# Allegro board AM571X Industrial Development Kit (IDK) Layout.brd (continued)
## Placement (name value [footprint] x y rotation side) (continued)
R97  0  [SM-7351-RES-0603]  23.49 123.78 270 top
R98  0  [SM-7351-RES-0402]  25.91 119.84 0 bottom
R99  49.9  [SM-7351-RES-0402]  17.84 123.53 0 bottom
R100  49.9  [SM-7351-RES-0402]  19.87 123.53 180 bottom
R101  49.9  [SM-7351-RES-0402]  22.61 127.21 90 bottom
R102  49.9  [SM-7351-RES-0402]  22.61 129.24 270 bottom
R103  4.87K  [SM-7351-RES-0402]  23.49 121.11 180 top
R104  2.2K  [SM-7351-RES-0402]  23.37 113.79 180 top
R106  0  [SM-7351-RES-0402]  6.48 129.88 90 bottom
R107  10K  [SM-7351-RES-0402]  43.05 86.82 270 bottom
R108  2.2K  [SM-7351-RES-0402]  23.37 116.08 180 top
R109  2.2K  [SM-7351-RES-0402]  23.37 114.94 180 top
R110  2.2K  [SM-7351-RES-0402]  23.37 111.51 180 top
R111  2.2K  [SM-7351-RES-0402]  23.37 112.65 180 top
R112  0  [SM-7351-RES-0402]  44.7 87.33 0 bottom
R113  62,1%  [SM-7351-RES-0402]  140.34 14.86 180 top
R114  0  [SM-7351-RES-0402]  141.61 10.41 0 top
R115  0  [SM-7351-RES-0402]  43.43 83.14 90 top
R116  2.2K  [SM-7351-RES-0402]  141.61 11.43 0 top
R117  0  [SM-7351-RES-0402]  45.97 83.14 90 top
R118  0  [SM-7351-RES-0402]  48.51 83.14 90 top
R119  0  [SM-7351-RES-0402]  51.05 83.14 90 top
R120  2.2K  [SM-7351-RES-0402]  29.59 93.17 270 top
R121  0  [SM-7351-RES-0402]  23.37 99.27 270 bottom
R122  0  [SM-7351-RES-0402]  7.7 117.55 180 bottom
R123  0  [SM-7351-RES-0402]  114.68 99.78 270 top
R124  0  [SM-7351-RES-0402]  118.49 99.9 270 top
R125  0  [SM-7351-RES-0402]  112.27 99.82 270 top
R126  0  [SM-7351-RES-0402]  119.63 99.95 270 top
R127  0  [SM-7351-RES-0402]  116.08 99.78 270 top
R128  0  [SM-7351-RES-0402]  117.47 99.9 270 top
R129  0  [SM-7351-RES-0402]  37.34 95.76 0 top
R130  0  [SM-7351-RES-0402]  40.51 96.52 0 top
R131  2.2K  [SM-7351-RES-0402]  27.69 95.33 270 top
R132  0  [SM-7351-RES-0402]  37.34 98.55 0 top
R133  0  [SM-7351-RES-0402]  34.42 101.35 180 bottom
R134  0  [SM-7351-RES-0402]  7.19 95.58 180 bottom
R135  0  [SM-7351-RES-0402]  34.42 102.49 180 bottom
R136  0  [SM-7351-RES-0402]  40 103 0 top
R137  0  [SM-7351-RES-0402]  37.34 104.77 0 top
R138  0  [SM-7351-RES-0603]  6.48 108.67 270 bottom
R139  0  [SM-7351-RES-0402]  37.34 97.28 0 top
R140  0  [SM-7351-RES-0402]  30.61 95.33 270 top
R141  0  [SM-7351-RES-0603]  29.34 101.55 270 bottom
R142  0  [SM-7351-RES-0402]  29.59 95.33 270 top
R143  49.9  [SM-7351-RES-0402]  24.38 106.89 270 top
R144  49.9  [SM-7351-RES-0402]  24.38 104.86 90 top
R145  49.9  [SM-7351-RES-0402]  24.38 102.82 270 top
R146  49.9  [SM-7351-RES-0402]  24.38 100.67 90 top
R147  4.87K  [SM-7351-RES-0402]  26.03 97.74 0 top
R148  0  [SM-7351-RES-0402]  40.51 100.71 0 top
R149  10K  [SM-7351-RES-0402]  186.72 83.14 180 bottom
R151  0  [SM-7351-RES-0402]  6.43 105.74 90 bottom
R152  2.2K  [SM-7351-RES-0402]  37.34 100.08 0 top
R153  10K  [SM-7351-RES-0402]  33.15 89.74 90 bottom
R154  0  [SM-7351-RES-0402]  34.8 89.24 0 bottom
R155  2.2K  [SM-7351-RES-0402]  37.34 103.76 180 top
R156  2.2K  [SM-7351-RES-0402]  40 104.01 180 top
R157  2.2K  [SM-7351-RES-0402]  37.34 102.36 180 top
R158  2.2K  [SM-7351-RES-0402]  37.34 101.3 180 top
R159  2.2K  [SM-7351-RES-0402]  28.19 77.55 270 top
R160  0  [SM-7351-RES-0402]  23.37 75.14 270 bottom
R161  0  [SM-7351-RES-0402]  7.75 93.43 180 bottom
R162  0  [SM-7351-RES-0402]  124.08 82.76 180 top
R163  0  [SM-7351-RES-0402]  124.08 81.62 180 top
R164  0  [SM-7351-RES-0402]  124.08 83.9 180 top
R165  0  [SM-7351-RES-0402]  37.34 77.68 0 top
R166  0  [SM-7351-RES-0402]  37.34 78.82 0 top
R167  0  [SM-7351-RES-0402]  120.27 83.57 180 top
R168  0  [SM-7351-RES-0402]  120.27 81.66 180 top
R169  0  [SM-7351-RES-0402]  124.08 85.17 180 top
R170  0  [SM-7351-RES-0402]  37.34 81.11 0 top
R171  0  [SM-7351-RES-0402]  37.34 83.52 0 bottom
R172  0  [SM-7351-RES-0402]  7.24 71.46 180 bottom
R173  0  [SM-7351-RES-0402]  37.34 84.66 0 bottom
R174  0  [SM-7351-RES-0402]  37.34 85.81 0 bottom
R175  0  [SM-7351-RES-0402]  37.34 86.95 0 bottom
R176  0  [SM-7351-RES-0402]  6.48 83.77 270 bottom
R177  0  [SM-7351-RES-0402]  37.34 79.96 0 top
R178  DNI  [SM-7351-RES-0402]  124.08 80.35 180 top
R179  0  [SM-7351-RES-0402]  30.61 77.55 270 top
R180  0  [SM-7351-RES-0603]  29.34 83.77 270 bottom
R181  0  [SM-7351-RES-0402]  29.59 77.55 270 top
R182  49.9  [SM-7351-RES-0402]  24.38 89.11 270 top
R183  49.9  [SM-7351-RES-0402]  24.38 87.08 90 top
R184  49.9  [SM-7351-RES-0402]  24.38 85.04 270 top
R185  49.9  [SM-7351-RES-0402]  24.38 82.89 90 top
R186  4.87K  [SM-7351-RES-0402]  28.19 77.55 90 bottom
R187  2.2K  [SM-7351-RES-0402]  37.34 82.5 180 top
R188  0  [SM-7351-RES-0402]  120.27 78.06 180 top
R189  0  [SM-7351-RES-0402]  6.48 81.62 90 bottom
R190  10K  [SM-7351-RES-0402]  28.19 71.2 90 bottom
R191  2.2K  [SM-7351-RES-0402]  37.34 86.95 180 top
R192  2.2K  [SM-7351-RES-0402]  37.34 85.81 180 top
R193  2.2K  [SM-7351-RES-0402]  37.34 84.66 180 top
R194  2.2K  [SM-7351-RES-0402]  37.34 83.52 180 top
R195  0  [SM-7351-RES-0402]  29.84 70.69 0 bottom
R196  0  [SM-7351-RES-0402]  43.31 74.5 90 top
R197  0  [SM-7351-RES-0402]  45.85 74.5 90 top
R198  0  [SM-7351-RES-0402]  48.39 74.5 90 top
R199  0  [SM-7351-RES-0402]  50.93 74.5 90 top
R200  2.2K  [SM-7351-RES-0402]  28.19 52.79 270 top
R201  2.2K  [SM-7351-RES-0402]  29.59 50.63 270 top
R202  0  [SM-7351-RES-0402]  23.37 50.37 270 bottom
R203  0  [SM-7351-RES-0402]  7.75 68.66 180 bottom
R204  0  [SM-7351-RES-0402]  78.36 95.97 0 top
R205  0  [SM-7351-RES-0402]  78.36 98 0 top
R206  0  [SM-7351-RES-0402]  78.36 94.95 0 top
R207  0  [SM-7351-RES-0402]  78.36 93.93 0 top
R208  0  [SM-7351-RES-0402]  78.36 92.92 0 top
R209  0  [SM-7351-RES-0402]  37.34 52.91 0 top
R210  0  [SM-7351-RES-0402]  78.36 96.98 0 top
R211  0  [SM-7351-RES-0402]  37.34 54.06 0 top
R212  0  [SM-7351-RES-0402]  37.34 56.34 0 top
R213  0  [SM-7351-RES-0402]  37.34 58.76 0 bottom
R214  0  [SM-7351-RES-0402]  7.24 46.69 180 bottom
R215  0  [SM-7351-RES-0402]  37.34 59.9 0 bottom
R216  0  [SM-7351-RES-0402]  37.34 61.04 0 bottom
R217  0  [SM-7351-RES-0402]  37.34 62.18 0 bottom
R218  0  [SM-7351-RES-0603]  6.48 59.39 270 bottom
R219  0  [SM-7351-RES-0402]  37.34 55.2 0 top
R220  DNI  [SM-7351-RES-0402]  124.08 74.8 180 top
R221  0  [SM-7351-RES-0402]  30.61 52.79 270 top
R222  0  [SM-7351-RES-0603]  29.34 59.01 270 bottom
R223  0  [SM-7351-RES-0402]  29.59 52.79 270 top
R224  49.9  [SM-7351-RES-0402]  24.38 64.34 270 top
R225  49.9  [SM-7351-RES-0402]  24.38 62.31 90 top
R226  49.9  [SM-7351-RES-0402]  24.38 60.28 270 top
R227  49.9  [SM-7351-RES-0402]  24.38 58.12 90 top
R228  4.87K  [SM-7351-RES-0402]  28.19 52.79 90 bottom
R230  0  [SM-7351-RES-0402]  124.08 77.17 180 top
R231  0  [SM-7351-RES-0402]  6.48 56.6 270 bottom
R232  2.2K  [SM-7351-RES-0402]  37.34 57.74 0 bottom
R233  10K  [SM-7351-RES-0402]  28.19 46.44 90 bottom
R234  0  [SM-7351-RES-0402]  29.84 45.93 0 bottom
R235  2.2K  [SM-7351-RES-0402]  37.34 62.18 180 top
R236  2.2K  [SM-7351-RES-0402]  37.34 61.04 180 top
R237  2.2K  [SM-7351-RES-0402]  37.34 59.9 180 top
R238  2.2K  [SM-7351-RES-0402]  37.34 58.76 180 top
R239  220  [SM-7351-RES-0402]  10.79 4.7 180 bottom
R240  220  [SM-7351-RES-0402]  17.4 4.7 180 bottom
R241  0  [SM-7351-RES-0402]  10.79 3.64 180 bottom
R242  220  [SM-7351-RES-0402]  10.79 11.43 180 bottom
R243  0  [SM-7351-RES-0402]  17.4 3.64 180 bottom
R244  220  [SM-7351-RES-0402]  17.4 11.43 180 bottom
R245  100K  [SM-7351-RES-0402]  10.79 2.62 0 bottom
R246  100K  [SM-7351-RES-0402]  17.4 2.62 0 bottom
R247  0  [SM-7351-RES-0402]  10.79 10.37 0 bottom
R248  0  [SM-7351-RES-0402]  17.4 10.37 0 bottom
R249  220  [SM-7351-RES-0402]  10.79 8 180 bottom
R250  220  [SM-7351-RES-0402]  17.4 8 180 bottom
R251  100K  [SM-7351-RES-0402]  10.79 9.35 0 bottom
R252  100K  [SM-7351-RES-0402]  17.4 9.35 0 bottom
R253  0  [SM-7351-RES-0402]  10.79 6.94 0 bottom
R254  0  [SM-7351-RES-0402]  17.4 6.94 0 bottom
R255  100K  [SM-7351-RES-0402]  10.79 5.92 0 bottom
R256  100K  [SM-7351-RES-0402]  17.4 5.92 0 bottom
R257  0  [SM-7351-RES-0402]  159 142.83 270 top
R258  0  [SM-7351-RES-0402]  162.71 133.56 90 top
R259  10K  [SM-7351-RES-0402]  177.95 133.56 270 bottom
R260  0  [SM-7351-RES-0402]  161.54 142.83 90 top
R261  0  [SM-7351-RES-0402]  164.11 133.56 270 top
R262  0  [SM-7351-RES-0402]  165.38 133.56 90 top
R263  0  [SM-7351-RES-0402]  166.65 133.56 270 top
R264  0  [SM-7351-RES-0402]  167.79 133.56 90 top
R265  0  [SM-7351-RES-0402]  169.19 133.56 270 top
R267  0  [SM-7351-RES-0402]  174.27 133.56 270 top
R269  0  [SM-7351-RES-0402]  176.81 133.56 270 top
R271  0  [SM-7351-RES-0402]  179.35 133.56 270 top
R273  0  [SM-7351-RES-0402]  181.89 133.56 270 top
R274  0  [SM-7351-RES-0402]  180.62 133.56 90 top
R275  0  [SM-7351-RES-0402]  185.57 133.56 90 top
R276  22  [SM-7351-RES-0402]  163.83 144.02 0 bottom
R277  0  [SM-7351-RES-0402]  188.11 133.56 90 top
R278  0  [SM-7351-RES-0603]  29.29 115.5 270 bottom
R279  1.5K  [SM-7351-RES-0402]  41.15 116.41 180 top
R280  100K  [SM-7351-RES-0402]  38.99 110.7 0 bottom
R281  22  [SM-7351-RES-0402]  84.84 103.12 270 top
R282  22  [SM-7351-RES-0402]  86.11 103.12 270 top
R283  22  [SM-7351-RES-0402]  87.38 103.12 270 top
R284  22  [SM-7351-RES-0402]  88.65 103.12 270 top
R285  22  [SM-7351-RES-0402]  36.86 111.76 270 top
R286  22  [SM-7351-RES-0402]  89.92 103.12 270 top
R287  22  [SM-7351-RES-0402]  91.19 103.12 270 top
R288  22  [SM-7351-RES-0402]  38.35 111.76 270 top
R289  22  [SM-7351-RES-0402]  35.46 111.76 270 top
R290  22  [SM-7351-RES-0402]  34.06 111.76 270 top
R291  22  [SM-7351-RES-0402]  32.66 111.76 270 top
R292  22  [SM-7351-RES-0402]  31.27 111.76 270 top
R293  220  [SM-7351-RES-0402]  33.02 145.37 90 bottom
R294  0  [SM-7351-RES-0402]  39.55 113.95 270 top
R295  0  [SM-7351-RES-0402]  41.15 117.43 0 top
R296  220  [SM-7351-RES-0402]  34.16 145.37 90 bottom
R297  4.7K  [SM-7351-RES-0402]  41.15 118.45 0 top
R298  12.1K, 1%  [SM-7351-RES-0402]  41.15 124.54 0 top
R299  10K  [SM-7351-RES-0402]  35.48 113.95 270 top
R300  DNI  [SM-7351-RES-0402]  163.83 145.29 0 bottom
R301  10K  [SM-7351-RES-0402]  34.09 113.95 270 top
R304  1K  [SM-7351-RES-0402]  36.88 113.95 270 top
R305  1M  [SM-7351-RES-0402]  45.5 103.06 270 bottom
R306  10K  [SM-7351-RES-0402]  32.77 114 270 top
R308  0  [SM-7351-RES-0402]  45.5 105.1 270 bottom
R309  10K  [SM-7351-RES-0402]  31.5 114 270 top
R310  33  [SM-7351-RES-0402]  37.21 103.89 180 bottom
R312  0  [SM-7351-RES-0402]  43.81 103.59 270 top
R313  33  [SM-7351-RES-0402]  38 105.1 180 bottom
R314  0  [SM-7351-RES-0402]  42.8 103.59 270 top
R315  33  [SM-7351-RES-0402]  38 107 180 bottom
R317  1K  [SM-7351-RES-0402]  38.28 113.95 270 top
R319  1K  [SM-7351-RES-0402]  28.45 124.03 0 top
R321  1K  [SM-7351-RES-0402]  28.45 121.11 0 top
R322  0  [SM-7351-RES-0603]  50.67 112.22 270 bottom
R324  100K  [SM-7351-RES-0402]  60.71 110.7 0 bottom
R325  22  [SM-7351-RES-0402]  120.27 104.9 270 top
R326  22  [SM-7351-RES-0402]  115.7 104.9 270 top
R327  22  [SM-7351-RES-0402]  117.98 104.9 270 top
R328  22  [SM-7351-RES-0402]  59.56 110.57 270 top
R329  22  [SM-7351-RES-0402]  58.17 110.57 270 top
R330  22  [SM-7351-RES-0402]  121.41 104.9 270 top
R331  22  [SM-7351-RES-0402]  116.84 104.9 270 top
R332  22  [SM-7351-RES-0402]  119.13 104.9 270 top
R333  22  [SM-7351-RES-0402]  56.77 110.57 270 top
R334  22  [SM-7351-RES-0402]  55.37 110.57 270 top
R335  22  [SM-7351-RES-0402]  53.98 110.57 270 top
R336  22  [SM-7351-RES-0402]  52.58 110.57 270 top
R337  220  [SM-7351-RES-0402]  54.74 145.37 90 bottom
R338  0  [SM-7351-RES-0402]  60.83 112.98 270 top
R339  0  [SM-7351-RES-0402]  62.99 117.05 0 top
R340  220  [SM-7351-RES-0402]  55.88 145.37 90 bottom
R341  12.1K, 1%  [SM-7351-RES-0402]  61.72 125.18 90 top
R342  4.7K  [SM-7351-RES-0402]  62.99 118.45 0 top
R343  10K  [SM-7351-RES-0402]  56.77 112.98 270 top
R345  10K  [SM-7351-RES-0402]  55.37 112.98 270 top
R348  1K  [SM-7351-RES-0402]  58.17 112.98 270 top
R349  1M  [SM-7351-RES-0402]  59.18 99.52 270 bottom
R351  0  [SM-7351-RES-0402]  59.18 101.68 270 bottom
R352  10K  [SM-7351-RES-0402]  53.98 112.98 270 top
R353  10K  [SM-7351-RES-0402]  52.58 112.98 270 top
R354  33  [SM-7351-RES-0402]  52.07 96.09 270 bottom
R356  0  [SM-7351-RES-0402]  57.78 106.13 90 bottom
R357  33  [SM-7351-RES-0402]  50.8 96.14 270 bottom
R358  0  [SM-7351-RES-0402]  56.64 106.13 90 bottom
R359  33  [SM-7351-RES-0402]  53.21 106.13 90 bottom
R361  1K  [SM-7351-RES-0402]  59.56 112.98 270 top
R363  1K  [SM-7351-RES-0402]  50.16 124.03 0 top
R364  10K  [SM-7351-RES-0402]  50.16 120.48 0 top
R366  10K  [SM-7351-RES-0402]  178.31 54.95 270 top
R367  0  [SM-7351-RES-0402]  127.89 75.27 180 top
R368  1.2K, MELF  [SMD_MELF0102]  178.97 58.17 180 bottom
R369  0  [SM-7351-RES-0402]  127.89 76.28 180 top
R370  1.2K, MELF  [SMD_MELF0102]  178.97 55.63 180 bottom
R371  0  [SM-7351-RES-0402]  85.47 92.92 0 top
R372  1.2K, MELF  [SMD_MELF0102]  178.97 53.09 180 bottom
R373  1.2K, MELF  [SMD_MELF0102]  178.97 48.01 180 bottom
R374  1.2K, MELF  [SMD_MELF0102]  178.97 50.55 180 bottom
R375  1.2K, MELF  [SMD_MELF0102]  178.97 45.47 180 bottom
R376  1.2K, MELF  [SMD_MELF0102]  178.97 42.93 180 bottom
R377  0  [SM-7351-RES-0402]  121.54 71.33 180 top
R378  1.2K, MELF  [SMD_MELF0102]  178.97 40.39 180 bottom
R379  49.9  [SMD_MELF0102]  187.58 77.6 270 top
R380  0  [SM-7351-RES-0402]  178.69 81.74 270 bottom
R381  0  [SM-7351-RES-0402]  179.71 81.74 270 bottom
R382  25K  [SM-7351-RES-0603]  182.37 81.49 0 bottom
R383  2.2K  [SM-7351-RES-0402]  127.89 69.3 0 top
R384  2.2K  [SM-7351-RES-0402]  127.89 72.47 0 top
R385  0  [SM-7351-RES-0402]  127.89 71.46 180 top
R386  150  [SM-7351-RES-0402]  176.15 37.46 0 top
R387  0  [SM-7351-RES-0402]  127.89 70.31 180 top
R388  150  [SM-7351-RES-0402]  176.15 35.31 0 top
R389  150  [SM-7351-RES-0402]  176.15 33.15 0 top
R390  150  [SM-7351-RES-0402]  176.15 30.99 0 top
R391  150  [SM-7351-RES-0402]  176.15 28.83 0 top
R392  150  [SM-7351-RES-0402]  176.15 26.67 0 top
R393  0  [SM-7351-RES-0402]  124.08 72.34 0 top
R394  0  [SM-7351-RES-0402]  124.08 70.69 0 top
R395  150  [SM-7351-RES-0402]  176.15 24.51 0 top
R396  150  [SM-7351-RES-0402]  176.15 22.35 0 top
R397  10K  [SM-7351-RES-0402]  95.25 148.37 180 bottom
R398  10K  [SM-7351-RES-0402]  95.25 149.39 180 bottom
R399  10K  [SM-7351-RES-0402]  86.49 148.63 0 bottom
R400  10K  [SM-7351-RES-0402]  86.49 147.61 0 bottom
R401  10K  [SM-7351-RES-0402]  95.25 147.36 180 bottom
R402  0  [SM-7351-RES-0402]  78.36 100.03 0 top
R403  0  [SM-7351-RES-0402]  78.36 103.08 0 top
R404  0  [SM-7351-RES-0402]  78.36 104.09 0 top
R405  0  [SM-7351-RES-0402]  78.36 105.11 0 top
R406  0  [SM-7351-RES-0402]  78.36 101.05 0 top
R407  0  [SM-7351-RES-0402]  78.36 102.06 0 top
R408  470K  [SM-7351-RES-0402]  96.9 138.08 90 bottom
R409  0  [SM-7351-RES-0402]  78.36 99.01 0 top
R410  0  [SM-7351-RES-0402]  75.69 141.31 270 bottom
R411  0  [SM-7351-RES-0402]  74.55 141.31 270 bottom
R412  10K  [SM-7351-RES-0402]  77.22 147.66 0 top
R413  10  [SM-7351-RES-0402]  74.68 148.34 270 bottom
R414  47K  [SM-7351-RES-0402]  75.82 148.34 270 bottom
R415  2.0, 1%  [SM-7351-RES-0603]  76.96 145.03 90 bottom
R416  0  [SM-7351-RES-0402]  77.22 148.93 0 top
R417  10K  [SM-7351-RES-0402]  76.83 141.31 270 bottom
R418  0  [SM-7351-RES-0402]  56.22 88.29 0 bottom
R419  100K  [SM-7351-RES-0402]  154.36 103.47 270 bottom
R420  10K  [SM-7351-RES-0402]  56.22 87.23 180 bottom
R421  DNI  [SM-7351-RES-0402]  10.67 32 90 bottom
R422  4.7K  [SM-7351-RES-0402]  183.9 91.95 90 bottom
R423  4.7K  [SM-7351-RES-0402]  176.28 91.31 180 top
R424  1.62M  [SM-7351-RES-0402]  157.66 106.27 90 bottom
R425  10K  [SM-7351-RES-0402]  145.16 135.97 90 top
R426  22  [SM-7351-RES-0402]  124.08 73.74 180 top
R427  180K  [SM-7351-RES-0402]  157.66 104.11 90 bottom
R428  10K  [SM-7351-RES-0402]  146.3 135.97 90 top
R429  100  [SM-7351-RES-0402]  186.56 91.06 270 bottom
R430  10K  [SM-7351-RES-0402]  144.02 135.97 90 top
R431  10K  [SM-7351-RES-0402]  142.75 125.18 0 bottom
R432  10K  [SM-7351-RES-0402]  142.24 121.75 0 bottom
R433  4.7K  [SM-7351-RES-0402]  175.9 83.69 0 top
R434  DNI  [SM-7351-RES-0402]  101.22 108.92 90 top
R435  18K  [SM-7351-RES-0402]  108.84 113.37 90 top
R436  18K  [SM-7351-RES-0402]  104.27 108.92 90 top
R437  DNI  [SM-7351-RES-0402]  106.81 113.37 90 top
R438  DNI  [SM-7351-RES-0402]  107.82 113.37 90 top
R439  DNI  [SM-7351-RES-0402]  103.25 108.92 90 top
R440  DNI  [SM-7351-RES-0402]  102.23 108.92 90 top
R441  DNI  [SM-7351-RES-0402]  110.87 113.37 90 top
R442  18K  [SM-7351-RES-0402]  109.86 113.37 90 top
R443  DNI  [SM-7351-RES-0402]  109.35 108.92 90 top
R444  DNI  [SM-7351-RES-0402]  110.36 108.92 90 top
R445  DNI  [SM-7351-RES-0402]  111.38 108.92 90 top
R446  DNI  [SM-7351-RES-0402]  112.39 108.92 90 top
R447  DNI  [SM-7351-RES-0402]  105.66 108.92 90 top
R448  DNI  [SM-7351-RES-0402]  113.41 108.92 90 top
R449  18K  [SM-7351-RES-0402]  106.68 108.92 90 top
R450  4.7K  [SM-7351-RES-0402]  186.44 89.41 0 bottom
R451  0  [SM-7351-RES-0402]  148.34 99.52 180 top
R453  10K  [SM-7351-RES-0402]  101.6 108.92 270 bottom
R454  DNI  [SM-7351-RES-0402]  108.84 113.37 270 bottom
R455  DNI  [SM-7351-RES-0402]  104.65 108.92 270 bottom
R456  10K  [SM-7351-RES-0402]  106.81 113.37 270 bottom
R457  10K  [SM-7351-RES-0402]  107.82 113.37 270 bottom
R458  10K  [SM-7351-RES-0402]  103.63 108.92 270 bottom
R459  10K  [SM-7351-RES-0402]  102.62 108.92 270 bottom
R460  10K  [SM-7351-RES-0402]  110.87 113.37 270 bottom
R461  DNI  [SM-7351-RES-0402]  109.86 113.37 270 bottom
R462  10K  [SM-7351-RES-0402]  109.35 108.92 270 bottom
R463  10K  [SM-7351-RES-0402]  110.36 108.92 270 bottom
R464  10K  [SM-7351-RES-0402]  111.38 108.92 270 bottom
R465  10K  [SM-7351-RES-0402]  112.39 108.92 270 bottom
R466  10K  [SM-7351-RES-0402]  105.66 108.92 270 bottom
R467  10K  [SM-7351-RES-0402]  113.41 108.92 270 bottom
R468  DNI  [SM-7351-RES-0402]  106.68 108.92 270 bottom
R472  DNI  [SM-7351-RES-0603]  177.04 4.19 180 top
R473  0  [SM-7351-RES-0402]  156.46 73.53 0 bottom
R474  0  [SM-7351-RES-0402]  155.63 76.33 0 top
R475  0  [SM-7351-RES-0402]  158.75 71.5 90 top
R476  0  [SM-7351-RES-0402]  160.91 71.5 90 top
R477  0  [SM-7351-RES-0402]  167.13 69.22 90 bottom
R478  0  [SM-7351-RES-0402]  165.1 71.5 90 bottom
R479  12K, 1%  [SM-7351-RES-0402]  156.01 81.41 180 top
R480  0  [SM-7351-RES-0402]  158.75 69.22 90 top
R481  0  [SM-7351-RES-0402]  160.78 69.22 90 top
R482  0  [SM-7351-RES-0402]  165.86 69.22 90 bottom
R483  0  [SM-7351-RES-0402]  167.13 71.5 90 bottom
R484  4.7K  [SM-7351-RES-0402]  164.08 71.5 270 bottom
R485  10K  [SM-7351-RES-0402]  155.63 77.35 180 top
R486  0  [SM-7351-RES-0402]  124.21 60.2 0 top
R487  0  [SM-7351-RES-0402]  124.21 62.48 0 top
R489  0  [SM-7351-RES-0402]  169.29 72.26 180 bottom
R491  4.7K  [SM-7351-RES-0402]  163.12 88.78 90 top
R492  0  [SM-7351-RES-0402]  165.28 88.78 270 top
R493  220  [SM-7351-RES-0402]  161.98 88.78 90 top
R494  10K  [SM-7351-RES-0402]  164.13 88.78 270 top
R495  2.2K  [SM-7351-RES-0402]  162.05 85.98 270 bottom
R496  10K  [SM-7351-RES-0402]  163.07 85.98 90 bottom
R497  0  [SM-7351-RES-0402]  79.38 87.46 180 top
R498  DNI  [SM-7351-RES-0402]  61.21 64.14 270 bottom
R499  0  [SM-7351-RES-0402]  74.68 75.56 0 top
R500  DNI  [SM-7351-RES-0402]  62.36 64.14 270 bottom
R502  33  [SM-7351-RES-0402]  171.7 21.29 180 bottom
R503  120  [SM-7351-RES-0402]  155.58 11.13 90 bottom
R504  33  [SM-7351-RES-0402]  172.85 18.75 180 bottom
R505  49.9K  [SM-7351-RES-0402]  86.87 129.24 180 top
R506  49.9K  [SM-7351-RES-0402]  86.87 126.45 180 top
R507  49.9K  [SM-7351-RES-0402]  86.87 125.3 180 top
R508  49.9K  [SM-7351-RES-0402]  89.53 131.91 90 top
R509  49.9K  [SM-7351-RES-0402]  88.39 131.91 90 top
R510  49.9K  [SM-7351-RES-0402]  86.87 128.1 180 top
R511  49.9K  [SM-7351-RES-0402]  86.87 123.65 180 top
R512  49.9K  [SM-7351-RES-0402]  86.87 122.51 180 top
R513  49.9K  [SM-7351-RES-0402]  95.25 105.03 270 bottom
R514  0  [SM-7351-RES-0402]  17.4 13.92 180 bottom
R515  100K  [SM-7351-RES-0402]  17.4 16.21 0 bottom
R539  10K  [SM-7351-RES-0402]  38.35 24.38 270 top
R542  10K  [SM-7351-RES-0402]  34.42 39.12 270 top
R543  10K  [SM-7351-RES-0402]  35.43 39.12 270 top
R544  10K  [SM-7351-RES-0402]  37.46 39.12 270 top
R545  10K  [SM-7351-RES-0402]  40 39.12 90 top
R546  10K  [SM-7351-RES-0402]  58.04 51.52 0 bottom
R547  DNI  [SM-7351-RES-0402]  45.97 59.82 0 bottom
R548  10K  [SM-7351-RES-0402]  53.59 48.47 270 bottom
R549  10K  [SM-7351-RES-0402]  54.61 48.47 270 bottom
R550  0  [SM-7351-RES-0402]  54.86 48.47 270 top
R551  10K  [SM-7351-RES-0402]  23.88 14.22 180 bottom
R553  10K  [SM-7351-RES-0402]  24.38 3.17 270 bottom
R554  0  [SM-7351-RES-0402]  174.12 76.28 270 top
R555  0  [SM-7351-RES-0402]  175.13 76.28 270 top
R556  DNI  [SM-7351-RES-0402]  124.08 64.39 0 top
R557  0  [SM-7351-RES-0402]  85.47 89.87 0 top
R558  0  [SM-7351-RES-0402]  65.15 22.86 180 top
R559  0  [SM-7351-RES-0402]  65.15 23.88 0 top
R560  DNI  [SM-7351-RES-0402]  58.8 12.45 90 top
R561  DNI  [SM-7351-RES-0402]  56.52 12.45 270 top
R562  DNI  [SM-7351-RES-0402]  57.66 12.45 90 top
R563  DNI  [SM-7351-RES-0402]  127.89 66.93 0 top
R564  0  [SM-7351-RES-0402]  118.11 85.22 0 top
R565  0  [SM-7351-RES-0402]  127.89 86.82 180 top
R566  0  [SM-7351-RES-0402]  160.53 100.46 90 bottom
R567  0  [SM-7351-RES-0402]  161.04 97.62 0 bottom
R568  0  [SM-7351-RES-0402]  52.58 48.47 270 bottom
R569  0  [SM-7351-RES-0402]  81.91 84.28 180 bottom
R570  10K  [SM-7351-RES-0402]  143.51 130.76 0 bottom
R571  10K  [SM-7351-RES-0402]  147.83 114.76 270 top
R572  0  [SM-7351-RES-0402]  131.44 114.76 90 top
R573  0  [SM-7351-RES-0402]  106.68 8.25 270 top
R574  0  [SM-7351-RES-0402]  112.9 99.78 270 bottom
R575  0  [SM-7351-RES-0402]  113.54 103.89 270 top
R576  0  [SM-7351-RES-0402]  119.51 114.94 180 top
R577  100K  [SM-7351-RES-0402]  114.43 8.89 180 top
R578  100K  [SM-7351-RES-0402]  114.43 7.62 0 top
R579  2.2K  [SM-7351-RES-0402]  130.18 10.16 180 top
R580  100  [SM-7351-RES-0402]  44.96 38.61 0 top
R581  100  [SM-7351-RES-0402]  78.61 77.17 90 top
R582  0  [SM-7351-RES-0402]  120.27 65.99 180 top
R583  0  [SM-7351-RES-0402]  110.74 62.69 90 top
R584  0  [SM-7351-RES-0402]  92.46 102.19 270 top
R585  0  [SM-7351-RES-0402]  161.04 96.6 0 bottom
R586  0  [SM-7351-RES-0402]  147.57 96.22 180 bottom
R587  0  [SM-7351-RES-0402]  175.9 84.96 180 top
R588  0  [SM-7351-RES-0402]  132.72 114.76 90 bottom
R589  220  [SM-7351-RES-0402]  10.79 18.16 180 bottom
R590  0  [SM-7351-RES-0402]  10.79 17.1 0 bottom
R591  100K  [SM-7351-RES-0402]  10.79 16.08 0 bottom
R592  100K  [SM-7351-RES-0402]  17.4 19.64 0 bottom
R593  0  [SM-7351-RES-0402]  17.4 20.66 0 bottom
R594  0  [SM-7351-RES-0402]  10.79 20.53 0 bottom
R595  100K  [SM-7351-RES-0402]  10.79 19.51 0 bottom
R596  220  [SM-7351-RES-0402]  10.79 14.86 180 bottom
R597  100K  [SM-7351-RES-0402]  17.4 12.91 0 bottom
R598  0  [SM-7351-RES-0402]  17.4 17.23 0 bottom
R599  100K  [SM-7351-RES-0402]  10.79 12.78 0 bottom
R600  0  [SM-7351-RES-0402]  10.79 13.8 180 bottom
R601  220  [SM-7351-RES-0402]  10.79 21.59 180 bottom
R602  220  [SM-7351-RES-0402]  17.4 18.29 180 bottom
R603  220  [SM-7351-RES-0402]  17.4 21.72 180 bottom
R604  220  [SM-7351-RES-0402]  17.4 14.99 180 bottom
R630  100  [SM-7351-RES-0402]  78.61 122.13 270 bottom
R631  100  [SM-7351-RES-0402]  77.34 120.6 270 bottom
R632  100  [SM-7351-RES-0402]  77.34 123.65 90 bottom
R633  100  [SM-7351-RES-0402]  78.61 119.08 90 bottom
R634  0  [SM-7351-RES-0402]  120.27 87.25 180 top
R636  0  [SM-7351-RES-0402]  124.08 86.31 180 top
R637  10K  [SM-7351-RES-0402]  161.04 98.63 180 bottom
R638  0  [SM-7351-RES-0402]  165.74 5.03 180 top
R639  0.05ohm1% Sense  [SM_RES_LVK12]  64.26 75.39 90 top
R640  0.047ohm1% Sense  [SM_RES_LVK12]  105.28 134.83 180 top
R641  0.015ohm0.5% Sense  [SM_RES_LVK12]  112.65 134.7 180 top
R642  0.024ohm0.5% Sense  [SM_RES_LVK12]  120.78 134.7 180 top
R643  0  [SM-7351-RES-0402]  74.93 73.66 0 top
R644  10K  [SM-7351-RES-0402]  86.61 107.4 90 top
R645  10K  [SM-7351-RES-0402]  93.85 103.25 90 top
R646  51K  [SM-7351-RES-0402]  157.39 117.9 90 top
R647  158K  [SM-7351-RES-0402]  161.07 121.58 90 top
R648  18.2K  [SM-7351-RES-0402]  161.07 119.42 90 top
R649  10K  [SM-7351-RES-0402]  29.34 39.12 90 top
R650  100  [SM-7351-RES-0402]  30.35 39.12 270 top
R652  0  [SM-7351-RES-0402]  34.29 24.38 270 top
R653  0  [SM-7351-RES-0402]  35.43 24.38 270 top
R654  10K  [SM-7351-RES-0402]  40.39 24.38 270 top
R655  100  [SM-7351-RES-0402]  41.4 24.38 90 top
R656  0  [SM-7351-RES-0603]  151.13 120.22 0 top
R657  0  [SM-7351-RES-0402]  137.01 128.34 0 bottom
R658  0  [SM-7351-RES-0402]  138.81 134.7 270 bottom
R659  0  [SM-7351-RES-0402]  94.61 99.95 270 top
R660  0  [SM-7351-RES-0402]  96.9 99.95 270 top
R661  0  [SM-7351-RES-0402]  119.63 74.25 180 bottom
R662  0  [SM-7351-RES-0402]  120.27 80.14 180 top
R663  0  [SM-7351-RES-0402]  105.54 113.37 270 top
R664  0  [SM-7351-RES-0402]  108.58 99.78 270 bottom
R665  0  [SM-7351-RES-0402]  104.52 113.37 270 top
R666  0  [SM-7351-RES-0402]  119.63 73.23 180 bottom
R669  0  [SM-7351-RES-0402]  113.54 99.78 90 top
R670  0  [SM-7351-RES-0402]  112.52 103.89 90 top
R671  0  [SM-7351-RES-0402]  111.38 99.78 90 bottom
R672  0  [SM-7351-RES-0402]  111.51 103.89 90 top
R673  0  [SM-7351-RES-0402]  127.89 85.81 180 top
R675  0  [SM-7351-RES-0402]  127.89 83.27 180 top
R676  0  [SM-7351-RES-0402]  127.89 84.54 180 top
R677  0  [SM-7351-RES-0402]  179.2 83.31 180 bottom
R678  0  [SM-7351-RES-0402]  70.99 117.18 180 bottom
R679  0  [SM-7351-RES-0402]  158.78 117.9 270 top
R680  10K, 1%  [SM-7351-RES-0402]  73.53 114.89 270 bottom
R681  19.6K  [SM-7351-RES-0402]  73.53 112.86 90 bottom
R682  0  [SM-7351-RES-0402]  68.45 23.75 90 top
R683  0  [SM-7351-RES-0402]  69.47 23.75 90 top
R684  0  [SM-7351-RES-0402]  120.27 67.01 0 top
R685  0  [SM-7351-RES-0402]  124.08 68.28 180 top
R686  0  [SM-7351-RES-0402]  100.84 99.82 90 top
R687  100  [SM-7351-RES-0402]  77.34 117.68 90 bottom
R688  0  [SM-7351-RES-0402]  103.38 99.69 90 top
R689  0  [SM-7351-RES-0402]  104.27 121.79 90 top
R690  0  [SM-7351-RES-0402]  104.65 99.69 90 top
R691  0  [SM-7351-RES-0402]  105.92 99.69 90 top
R692  0  [SM-7351-RES-0402]  103.89 102.49 90 top
R693  220  [SM-7351-RES-0402]  72.64 105.54 180 bottom
R694  0  [SM-7351-RES-0402]  81.03 100.28 90 bottom
R695  100K  [SM-7351-RES-0402]  79.76 100.28 90 bottom
R696  220  [SM-7351-RES-0402]  76.07 105.54 180 bottom
R697  100K  [SM-7351-RES-0402]  76.45 100.28 90 bottom
R698  0  [SM-7351-RES-0402]  77.47 100.28 270 bottom
R699  220  [SM-7351-RES-0402]  79.5 105.54 180 bottom
R700  100K  [SM-7351-RES-0402]  72.9 100.28 90 bottom
R701  0  [SM-7351-RES-0402]  74.04 100.28 90 bottom
R702  220  [SM-7351-RES-0402]  68.83 103.5 180 bottom
R703  0  [SM-7351-RES-0402]  70.74 91.14 90 bottom
R704  100K  [SM-7351-RES-0402]  69.6 91.14 90 bottom
R705  220  [SM-7351-RES-0402]  69.22 89.41 180 bottom
R706  100K  [SM-7351-RES-0402]  69.47 84.03 90 bottom
R707  0  [SM-7351-RES-0402]  70.61 84.03 270 bottom
R708  220  [SM-7351-RES-0402]  67.18 95.12 180 bottom
R709  100K  [SM-7351-RES-0402]  69.09 98.25 90 bottom
R710  0  [SM-7351-RES-0402]  70.23 98.25 90 bottom
R729  100, 1%  [SM-7351-RES-0402]  161.54 7.96 90 top
R730  100, 1%  [SM-7351-RES-0402]  183.77 86.87 90 bottom
R732  0  [SM-7351-RES-0402]  106.93 99.69 90 top
R733  0  [SM-7351-RES-0402]  106.3 102.49 90 top
R734  0  [SM-7351-RES-0402]  105.03 102.49 90 top
R741  10K  [SM-7351-RES-0402]  95 135.84 90 bottom
R742  0  [SM-7351-RES-0603]  140.34 126.07 270 bottom
R743  0  [SM-7351-RES-0402]  103.38 143.38 270 top
R744  0  [SM-7351-RES-0402]  105.41 143.38 270 top
R745  0  [SM-7351-RES-0402]  107.31 143.38 270 top
R746  0  [SM-7351-RES-0402]  109.35 143.38 270 top
R747  0  [SM-7351-RES-0402]  111.38 143.38 270 top
R748  0  [SM-7351-RES-0402]  30.61 93.17 90 top
R749  0  [SM-7351-RES-0402]  115.32 143.51 270 top
R750  0  [SM-7351-RES-0402]  117.35 143.51 270 top
R751  0  [SM-7351-RES-0402]  119.38 143.51 270 top
R752  0  [SM-7351-RES-0402]  121.28 143.51 270 top
R753  0  [SM-7351-RES-0402]  123.32 143.51 270 top
R787  0  [SM-7351-RES-0402]  83.57 86.95 0 top
R788  100  [SM-7351-RES-0402]  8.76 44.4 0 bottom
R789  10K  [SM-7351-RES-0402]  8.76 43.31 0 bottom
R790  10K  [SM-7351-RES-0402]  16.89 42.88 90 top
R791  10K  [SM-7351-RES-0402]  18.41 46.82 180 top
R792  0  [SM-7351-RES-0402]  56.22 86.08 0 bottom
R793  20.5K  [SM-7351-RES-0402]  124.59 43.9 0 top
R794  0  [SM-7351-RES-0402]  140.69 122.38 270 bottom
R795  0  [SM-7351-RES-0402]  68.33 20.4 90 bottom
R796  0  [SM-7351-RES-0402]  65.66 23.07 90 bottom
R797  0  [SM-7351-RES-0402]  120.27 80.73 180 bottom
R798  10K  [SM-7351-RES-0402]  165.74 3.89 0 top
R799  10K  [SM-7351-RES-0402]  100.33 124.16 90 top
R800  10K  [SM-7351-RES-0402]  85.47 91.9 180 top
R803  0  [SM-7351-RES-0402]  106.3 105.03 90 top
R804  DNI  [SM-7351-RES-0402]  130.68 68.71 0 top
R805  DNI  [SM-7351-RES-0402]  130.68 70.36 0 top
R806  100  [SM-7351-RES-0402]  179.2 88.9 180 bottom
R807  0  [SM-7351-RES-0402]  105 84.25 270 bottom
R833  10K  [SM-7351-RES-0402]  138.3 113.03 270 bottom
R834  10K  [SM-7351-RES-0402]  153.8 140.59 90 top
R835  10K  [SM-7351-RES-0402]  146.3 138.43 270 top
R836  1M  [SM-7351-RES-0402]  33.53 16.64 180 bottom
R837  1M  [SM-7351-RES-0402]  5.46 31.5 0 top
R838  0  [SM-7351-RES-0402]  131.32 143.51 90 top
R839  0  [SM-7351-RES-0402]  133.35 143.51 90 top
R840  0  [SM-7351-RES-0402]  135.38 143.51 90 top
R841  0  [SM-7351-RES-0402]  137.41 143.51 90 top
R842  0  [SM-7351-RES-0402]  141.48 143.51 90 top
R843  0  [SM-7351-RES-0402]  143.51 143.51 90 top
R844  0  [SM-7351-RES-0402]  145.54 143.51 90 top
R845  0  [SM-7351-RES-0402]  147.57 143.51 90 top
R846  DNI  [SM-7351-RES-0402]  130.3 143.51 90 top
R847  DNI  [SM-7351-RES-0402]  132.33 143.51 90 top
R848  DNI  [SM-7351-RES-0402]  134.37 143.51 90 top
R849  DNI  [SM-7351-RES-0402]  136.4 143.51 90 top
R850  DNI  [SM-7351-RES-0402]  140.46 143.51 90 top
R851  DNI  [SM-7351-RES-0402]  142.49 143.51 90 top
R852  DNI  [SM-7351-RES-0402]  144.53 143.51 90 top
R853  DNI  [SM-7351-RES-0402]  146.56 143.51 90 top
R854  0  [SM-7351-RES-0402]  145.67 125.98 270 bottom
R855  0  [SM-7351-RES-0402]  154.31 143.51 90 top
R856  0  [SM-7351-RES-0402]  157.35 143.51 90 top
R857  0  [SM-7351-RES-0402]  150.24 143.51 270 top
R858  0  [SM-7351-RES-0402]  152.27 143.51 270 top
R859  0  [SM-7351-RES-0402]  156.34 143.51 270 top
R860  0  [SM-7351-RES-0402]  156.34 143.51 270 bottom
R861  0  [SM-7351-RES-0402]  130.3 143.38 270 bottom
R862  0  [SM-7351-RES-0402]  133.35 143.38 270 bottom
R863  0  [SM-7351-RES-0402]  135.38 143.38 270 bottom
R864  0  [SM-7351-RES-0402]  138.43 143.51 270 top
R865  DNI  [SM-7351-RES-0402]  131.32 143.38 270 bottom
R866  DNI  [SM-7351-RES-0402]  132.33 143.38 270 bottom
R867  DNI  [SM-7351-RES-0402]  134.37 143.38 270 bottom
R868  DNI  [SM-7351-RES-0402]  139.45 143.51 270 top
R869  0  [SM-7351-RES-0402]  145.42 143.38 270 bottom
R870  0  [SM-7351-RES-0402]  147.45 143.38 270 bottom
R871  DNI  [SM-7351-RES-0402]  151.26 143.51 270 top
R872  DNI  [SM-7351-RES-0402]  153.29 143.51 270 top
R873  DNI  [SM-7351-RES-0402]  155.32 143.51 270 top
R874  DNI  [SM-7351-RES-0402]  112.39 143.38 90 bottom
R875  DNI  [SM-7351-RES-0402]  114.3 143.38 90 bottom
R876  DNI  [SM-7351-RES-0402]  116.33 143.38 90 bottom
R877  DNI  [SM-7351-RES-0402]  104.39 143.38 90 bottom
R878  DNI  [SM-7351-RES-0402]  106.43 143.38 90 bottom
R879  DNI  [SM-7351-RES-0402]  110.36 143.38 90 bottom
R880  DNI  [SM-7351-RES-0402]  108.33 143.38 90 bottom
R881  DNI  [SM-7351-RES-0402]  84.84 102.11 270 top
R882  DNI  [SM-7351-RES-0402]  89.92 102.11 270 top
R883  DNI  [SM-7351-RES-0402]  86.11 102.11 270 top
R884  DNI  [SM-7351-RES-0402]  91.19 102.11 270 top
R885  DNI  [SM-7351-RES-0402]  87.38 102.11 270 top
R886  DNI  [SM-7351-RES-0402]  88.65 102.11 270 top
R887  DNI  [SM-7351-RES-0402]  38.35 110.74 270 top
R888  0  [SM-7351-RES-0402]  124.33 143.38 90 bottom
R889  0  [SM-7351-RES-0402]  126.36 143.38 90 bottom
R890  0  [SM-7351-RES-0402]  128.4 143.38 90 bottom
R891  0  [SM-7351-RES-0402]  148.59 143.51 90 top
R892  DNI  [SM-7351-RES-0402]  167.51 149.99 90 top
R893  DNI  [SM-7351-RES-0402]  169.8 149.99 90 top
R894  499  [SM-7351-RES-0402]  36.07 96.65 90 bottom
R895  10K  [SM-7351-RES-0402]  35.43 94.61 180 bottom
R896  DNI  [SM-7351-RES-0402]  34.92 96.65 90 bottom
R897  40.2K  [SM-7351-RES-0402]  38.1 91.31 180 bottom
R898  499  [SM-7351-RES-0402]  113.92 125.48 180 bottom
R899  10K  [SM-7351-RES-0402]  115.95 124.84 270 bottom
R900  DNI  [SM-7351-RES-0402]  113.92 124.33 180 bottom
R901  40.2K  [SM-7351-RES-0402]  119.25 127.51 270 bottom
R902  10K  [SM-7351-RES-0402]  164.85 149.1 270 bottom
R903  22  [SM-7351-RES-0402]  172.97 143 180 bottom
R904  0  [SM-7351-RES-0402]  143.13 64.64 0 top
R905  DNI  [SM-7351-RES-0402]  163.83 146.56 180 bottom
R906  DNI  [SM-7351-RES-0402]  139.17 122.3 0 bottom
R907  DNI  [SM-7351-RES-0402]  80.9 86.49 180 bottom
R908  0  [SM-7351-RES-0402]  80.9 85.34 180 bottom
R909  DNI  [SM-7351-RES-0402]  95 97.66 90 bottom
R910  0  [SM-7351-RES-0402]  92.08 97.66 90 bottom
R911  10K  [SM-7351-RES-0402]  165.99 52.45 180 bottom
R912  10K  [SM-7351-RES-0402]  166.24 46.1 90 bottom
R913  DNI  [SM-7351-RES-0402]  157.61 42.04 180 bottom
R914  0  [SM-7351-RES-0402]  157.61 41.02 180 bottom
R915  DNI  [SM-7351-RES-0402]  157.61 44.96 180 bottom
R916  0  [SM-7351-RES-0402]  157.61 43.94 180 bottom
R917  DNI  [SM-7351-RES-0402]  157.61 46.74 180 bottom
R918  0  [SM-7351-RES-0402]  157.61 47.75 180 bottom
R919  DNI  [SM-7351-RES-0402]  79.88 89.15 270 top
R920  0  [SM-7351-RES-0402]  63.5 64.14 270 bottom
R921  0  [SM-7351-RES-0402]  66.93 79.63 180 top
R922  DNI  [SM-7351-RES-0402]  96.01 103.25 90 top
R923  DNI  [SM-7351-RES-0402]  95 103.25 270 top
R924  10K  [SM-7351-RES-0402]  138.68 69.22 0 top
R925  0  [SM-7351-RES-0402]  105.41 121.79 90 top
R927  47K  [SM-7351-RES-0402]  158.24 113.41 0 top
R928  10K  [SM-7351-RES-0402]  151.38 114.43 0 top
R929  DNI  [SM-7351-RES-0402]  154.31 143.51 90 bottom
R930  DNI  [SM-7351-RES-0402]  157.35 143.51 90 bottom
R931  DNI  [SM-7351-RES-0402]  143.13 116.59 180 bottom
SCKT1  DNI AM57XX ABC Socket  [SCK-SG-BGA-6334]  102.23 81.99 270 top
SW1  B3SL  [SW_B3SL-1022P]  166.88 44.15 180 top
SW2  B3SL  [SW_B3SL-1022P]  166.88 53.42 180 top
SW3  B3SL  [SW_B3SL-1022P]  155.7 53.42 180 top
TP1  TP  [TH_TP_5002]  175.92 129.88 0 top
TP2  TP1mm  [TP_SMD1MMCIRCLE]  149.48 114.81 0 top
TP3  TP1mm  [TP_SMD1MMCIRCLE]  149.61 111.63 0 top
TP6  TP1mm  [TP_SMD1MMCIRCLE]  147.57 111.63 0 top
TP7  TP1mm  [TP_SMD1MMCIRCLE]  153.67 110.62 0 top
TP8  TP  [TH_TP_5002]  80.26 149.86 0 top
TP9  TP  [TH_TP_5002]  187.86 120.6 0 top
TP10  TP  [TH_TP_5002]  75.22 2.67 0 top
TP11  TP  [TH_TP_5002]  2.67 14.1 0 top
TP16  TP1mm  [TP_SMD1MMCIRCLE]  43.56 119.84 0 top
TP17  TP1mm  [TP_SMD1MMCIRCLE]  63.25 120.1 0 top
TP18  TP1mm  [TP_SMD1MMCIRCLE]  173.23 77.98 0 top
TP19  TP1mm  [TP_SMD1MMCIRCLE]  69.09 79.63 0 top
TP20  TP1mm  [TP_SMD1MMCIRCLE]  36.45 42.93 0 top
TP21  TP1mm  [TP_SMD1MMCIRCLE]  148.08 138.26 0 top
TP22  TP1mm  [TP_SMD1MMCIRCLE]  126.49 78.06 0 top
TP23  TP1mm  [TP_SMD1MMCIRCLE]  128.4 78.06 0 top
TP24  TP1mm  [TP_SMD1MMCIRCLE]  162.36 95.38 0 top
TP25  TP  [TH_TP_5002]  122.3 110.87 0 top
TP26  TP  [TH_TP_5002]  145.16 105.79 0 top
TP27  TP1mm  [TP_SMD1MMCIRCLE]  151.77 112.39 270 top
U1  AM571X_ABC  [BGA23X23-760-117M]  102.23 81.62 270 top
U2  SN74LVC1G07  [SC70-5-43M]  166.88 42.8 90 bottom
U3  TPS6590377ZWSR  [BGA12X12-169-55M]  139.45 125.94 0 top
U4  S25FL256S  [SOIC_16PIN_DW]  95.5 116.41 180 top
U5  MT41K256M16HA  [BGA9X14-96]  85.98 31.88 0 top
U6  MT41K256M16HA  [BGA9X14-96]  116.46 31.88 0 top
U7  MT41K256M16HA  [BGA9X14-96]  101.22 31.88 0 top
U8  TPS51200  [DRCPSO_10PIN]  107.82 14.73 180 top
U9  TLK105L  [QFN5X5-32-39M]  21.34 118.7 0 bottom
U13  TLK105L  [QFN5X5-32-39M]  31.5 100.41 270 top
U15  TLK105L  [QFN5X5-32-39M]  31.5 82.63 270 top
U17  TLK105L  [QFN5X5-32-39M]  31.5 57.87 270 top
U18  PicoHaptics 304-100  [PICO_304-100]  140.84 17.65 180 top
U19  SN74LVC1G04  [SC70-5-43M]  187.22 85.81 90 bottom
U21  KSZ9031RN  [QFN7X7-48]  35.18 120.86 270 top
U22  SN74LVC1G07  [SC70-5-43M]  35.69 110.11 0 bottom
U23  CDCE913  [TSSOP5X4-14-47M]  41.94 103.45 90 bottom
U24  KSZ9031RN  [QFN7X7-48]  56.9 120.86 270 top
U25  CDCE913  [TSSOP5X4-14-47M]  55.88 100.67 90 bottom
U26  SN74LVC1G07  [SC70-5-43M]  57.4 110.11 0 bottom
U28  SN74LVC1G07  [SC70-5-43M]  178.94 58.04 270 top
U30  TPD6E001  [U_10_RSE]  90.8 147.86 90 bottom
U32  TPS61081DRC  [U_10_DRC]  74.04 144.61 0 bottom
U33  CAT24C256W  [SOIC_8]  10.03 26.29 180 bottom
U34  SN74LVC1G00DCK  [U_5_DCK]  166.42 82.3 180 bottom
U36  TPD2E001  [U_5_DRL]  182.27 14.1 180 top
U37  FT2232HL  [LQFP64PIN]  164.39 80.14 0 top
U38  93LC56B  [SOIC_8]  168.91 93.3 90 bottom
U39  DNI SN74LVC1G07  [SC70-5-43M]  60.58 67.18 270 bottom
U40  R1Z-3.305HP  [SMD15X11-6-374M]  164.59 23.32 0 top
U41  ISO1050  [SO9X6-8-191M]  163.45 20.02 270 bottom
U43  EMMC16G  [BGA11X13-153-39M]  95.63 126.7 270 bottom
U44  74LVC1G125  [SC70-5-43M]  42.04 41.53 270 top
U45  CDCM9102  [QFN5X5-32TI-39M]  53.72 53.29 180 bottom
U46  TPD12S016  [PW_24PIN_TSSOP]  64.64 18.16 180 top
U47  DNI SN74LVC1G07  [SC70-5-43M]  125.35 46.23 0 top
U48  TPD1E10B06  [TPD1E10B06-2L]  170.31 53.55 0 bottom
U49  TPD1E10B06  [TPD1E10B06-2L]  170.56 41.15 270 bottom
U50  TPD1E10B06  [TPD1E10B06-2L]  149.73 51.39 180 top
U52  TPS76650  [SOIC_8]  97.79 10.41 90 bottom
U62  TPS63010  [U_20_DSBGA]  155.37 106.14 90 bottom
U63  SN74AVC4T245  [U_16_PW]  172.72 85.09 270 bottom
U64  TPD2EUSB30  [SOT1X1-3-20M]  43.05 17.65 90 bottom
U65  SN74AVC2T244  [SON2X1-8-16M]  173.99 72.95 90 top
U66  TPS2065D  [U_8_D]  26.29 8.89 180 bottom
U68  SN74LVC1G08  [SM-SO-SC70-5]  42.42 89.62 180 bottom
U69  SN74LVC1G08  [SM-SO-SC70-5]  31.12 90.12 180 bottom
U70  SN74LVC1G08  [SM-SO-SC70-5]  26.16 71.68 180 bottom
U71  SN74LVC1G08  [SM-SO-SC70-5]  26.16 46.82 180 bottom
U72  SN65HVS882  [U_28_PWP]  181.89 75.82 0 bottom
U73  TPIC2810  [U_16_D]  168.15 34.37 0 bottom
U74  ISO1176T  [U_16_DW]  122.3 8.25 90 top
U75  SN74AVC2T244  [SON2X1-8-16M]  168 61.3 90 bottom
U76  TPS71712  [SMDSC70-5]  151.38 100.16 270 top
U77  SN65HVD78D  [SOIC_8]  177.17 8.84 0 bottom
U78  SN74LVC1G07  [SC70-5-43M]  187.1 94.19 90 bottom
U79  TPS61085  [MSOP3X3-8-43M]  158.4 122.59 90 top
U80  TPD1E10B06  [TPD1E10B06-2L]  92.2 8.51 180 top
U81  TPD1E10B06  [TPD1E10B06-2L]  94.61 8.51 0 top
U82  TPD1E10B06  [TPD1E10B06-2L]  160.78 11.43 180 top
U83  TPD1E10B06  [TPD1E10B06-2L]  163.2 11.43 0 top
U84  TPD1E10B06  [TPD1E10B06-2L]  96.9 135.04 270 top
U85  SN74LVC1G08  [SM-SO-SC70-5]  42.01 47.09 180 top
U86  LP38693ADJ  [SOT-223-5]  68.33 112.86 180 bottom
U87  TPD1E10B06  [TPD1E10B06-2L]  158.37 13.34 0 bottom
U88  TPD1E10B06  [TPD1E10B06-2L]  156.21 13.34 180 bottom
U89  TC358778  [BGA7X7-80-39M]  154.31 95.97 90 bottom
U93  TPD4S012  [U_6_DRY]  6.6 40.59 270 top
U94  TPS2051BD  [U_8_D]  20.83 41.99 180 top
U96  SN74LVC1G07  [SC70-5-43M]  150.11 140.72 0 top
U97  SN74LVC1G07  [SC70-5-43M]  164.34 50.04 180 bottom
U98  SN74LVC1G08  [SM-SO-SC70-5]  163.58 43.94 0 bottom
U99  SN74LVC1G07  [SC70-5-43M]  159.64 74.68 180 bottom
U100  SN74AVC2T245  [UQFN1X2-10-22M]  149.35 70.74 90 top
U101  TLV1117-33CDCY  [SOT223-4-71M]  176.15 10.54 270 top
U102  SN74CBTLV16292GR  [TSSOP6X14-56-47M]  137.8 86.36 0 top
U103  SN74CBTLV16292GR  [TSSOP6X14-56-47M]  137.8 101.85 0 top
U104  SN74CBTLV3257PWR  [U_16_PW]  136.4 91.19 90 bottom
U105  TPS3808G50DBV  [U_6_DBV]  154.81 113.41 270 top
X1  20.000 MHZ  [OSC7X5-71M]  169.93 147.57 0 bottom
Y1  20MHz  [XTAL2X3-30M]  73.91 82.38 0 top
Y2  16.384MHz  [XTAL3225-39M]  136.27 138 180 top
Y3  25MHz  [SM_OSC_ABM3]  49.18 103.19 270 bottom
Y4  25MHz  [SM_OSC_ABM3]  62.86 99.65 270 bottom
Y5  12MHz  [SM_OSC_ABM3]  151.43 84.33 270 top
Y6  32.768KHz MC-306  [MC-306]  72.26 88.09 180 top
Y7  25MHz  [ASF_SMD3_2X5MM]  45.85 57.1 270 bottom

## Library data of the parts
C1 C2 = 1C_24pFCapacitor50V5%SMD0402: Tolerance: TOLERANCE; User Part Number: USERPART#
C3 C7-C12 C28-C32 C34-C43 C48-C51 C55-C63 C65-C79 C81 C105 C112-C115 C118 C120 C127 C130 C137 C139 C142 C144 C151 C152 C165 C169-C171 C186 C190-C192 C195 C207 C210 C214 C216 C219-C221 C225 C226 C228-C230 C232-C236 C238-C240 C242 C248 C251 C255-C258 C261-C264 C267 C308-C310 C315 C319 C321 C322 C324 C326-C332 C334-C339 C341-C346 C348 C349 C351-C353 C355-C358 C360 C362-C365 C367-C374 C376-C381 C385 C386 C388-C391 C393 C394 C400 C401 C403-C406 C408-C410 C420 C424-C430 C443 C444 C448 C451 C453 C469 C470 C480-C482 C485-C487 C547 C548 C563 C564 C566 C567 C569-C575 C577 C578 C583 = 1C_0.01uFCapacitor16V10%0402: Tolerance: TOLERANCE; User Part Number: USERPART#
C4 C5 C209 C265 C286-C293 C296-C298 C350 C407 C442 C445-C447 C484 C565 C568 C576 = 1C_1uFCapacitor10V10%0402: Tolerance: TOLERANCE; User Part Number: USERPART#
C6 C22 C88 C91 C92 C95-C97 C110 C125 C136 C149 C154 C156 C159 C161 C163 C168 C175 C177 C180 C182 C184 C189 C215 C222 C266 C305-C307 C317 C320 C333 C340 C347 C354 C361 C375 C384 C387 C395 C396 C413 C414 C433 C458 C483 = 1C_10uFCapacitor16V10%0805
C20 C21 C44-C47 C53 C54 C80 C82 C83 C85 C87 C89 C90 C93 C94 C98-C100 C102-C104 C107-C109 C111 C116 C117 C119 C122-C124 C126 C128 C129 C132-C135 C138 C140 C141 C143 C145 C147 C148 C150 C153 C155 C160 C162 C164 C174 C176 C181 C183 C185 C211 C213 C223 C245 C252 C313 C314 C415 C417 C454-C457 C460 C557 C559 C579 C580 = 1C_0.1uFCapacitor16V10%0402: Tolerance: TOLERANCE; User Part Number: USERPART#
C23 C316 C421 C459 = 1C_1uFCapacitor50V10%0603
C24 C411 C412 C441 = 1C_100uFCapacitor16V20%ElecPoly
C25 C26 = 1C_27pFCapacitor10V5%0402: Tolerance: TOLERANCE; User Part Number: USERPART#
C27 C166 C167 C187 C188 C303 C304 C431 C432 C434 C449 = 1C_0.1uFCapacitor50V10%0402: Tolerance: TOLERANCE; User Part Number: USERPART#
C33 C52 C64 C418 C419 = 1C_22uFCapacitor16V10%0805
C84 C86 C196 C558 C560 = 1C_0.001uFCapacitor50V5%0402: Tolerance: TOLERANCE; User Part Number: USERPART#
C101 = 1C_10pFCapacitor50V1%smd0402: Tolerance: TOLERANCE; User Part Number: USERPART#
C106 C121 C131 C146 = 1C_4700pFCapacitor50V10%0402: Tolerance: TOLERANCE; User Part Number: USERPART#
C157 C158 C178 C179 C561 = 1C_47uFCapacitor16V20%1206
C172 C173 C193 C194 C243 C244 = 1C_18pFCapacitor16V10%0402: Tolerance: TOLERANCE; User Part Number: USERPART#
C197-C204 = 1C_0.022uFCapacitor16Vsmd0402: Tolerance: TOLERANCE; User Part Number: USERPART#
C205 C208 C224 C464-C468 C471 C472 C479 = 1C_2.2uF16V10%SMD0805
C206 C435 = 1C_10uFCapacitor50V10%1206
C212 C217 C231 C237 C241 C272-C275 C281-C285 C416 C546 = 1C_4.7uFCapacitor16V10%0603
C218 = 1C_4.7uFCapacitor50V20%0805
C246 C247 = 1C_15pFCapacitor50V10%smd0402: Tolerance: TOLERANCE; User Part Number: USERPART#
C249 C250 = 1C_3.3uFCapacitor16V10%0603
C253 C254 = 1C_100pFCapacitor16V10%0402: Tolerance: TOLERANCE; User Part Number: USERPART#
C268-C271 C276-C280 = 1C_47uFCapacitor10V20%SMD1206
C301 C302 C318 C382 C383 C392 C399 C402 C562 = 1C_2.2uFCapacitor6.3V20%X5R0402: Tolerance: TOLERANCE; User Part Number: USERPART#
C311 C545 = 1C_150uFCapacitor10V10%2917
C323 C325 = 4.7uFCapacitor16V20%Tant
C436-C439 C477 C478 C581 C582 = 1C_0.1uFCapacitor16V10%0402: Tolerance: TOLERANCE; User Part Number: USERPART#; signal model: 1C_0.1UFCAPACITOR16V10%0402_SM-_0.1uF
C450 C452 = 1C_10uFCapacitor6.3V20%0603
C461 C462 = 1C_10uFCapacitor35V10%0805
C463 = 1C_1.1nFCapacitor50V5%0603
C473-C475 = 1C_47uFCapacitor10V10%smd2917: User Part Number: P/N*; Tolerance: TOL*
C476 = 1C_2.2uFCapacitor10V20%smd0402: Tolerance: TOLERANCE; User Part Number: USERPART#
D1 = 1E_Diode_15ARect_rev45V
D2 = 1E_Diode_SMCJ26CA
D3 D4 = Diode200mA250V
D5-D13 = 1F_LED_Green
D14 D15 = Diode_500mA20V
D16-D19 D22 D23 = 1F_LED_Tricolor_RedGreenYellow
D20 = 1E_Diode_1ARect_Rev20V
D24 D25 = TLVH431_4
F1 = 1P_Fuse_8A
FB1-FB8 = 1L_FerriteBead_600mA10ohm
FB9-FB11 = 1L_FerriteBead_220ohm2A
FB12 FB13 FB19 = 1L_FerBead_180ohm200mA
J1 = 2J_Conn_PwrJack_RAPC712
J2 = 2C_Conn_LeadScrewDown_2pin
J3 J5 J6 J8 = 2J_ConnectorRJ45_10_100MbAMDIX
J4 J7 J38 = 2H_Header_5x1
J9 = 2H_Header12x2
J10 J12 = 2J_ConnectorRJ45_Gigabit
J14 = 2C_Conn_DSUB9F
J15 = 2C_Conn_microSD_8: User Part Number: X; Tolerance: X
J16 = 2C_Conn_FFC_0.5mm_32pos
J17 = 2C_Conn_FFC_0.5mm_6pos
J18 = 2H_Header10x2_CJTAG
J19 J45 = 2C_MicroUSBAB
J21 = 2H_Header30x2_female_2mm
J23 = 2C_Connector_USB3_0_A_0
J24 = 2C_Conn_HDMI_TypeA
J37 = 2H_Header15x2_0.1in_Female
J39 = 2H_Header_3x1
J40-J44 J49-J51 = 2H_Header_2x1
J46 = 2H_Header_4x1
J52 = 2C_PCIEConnector_x4SMT_10061913
J53 = Terminal Block_0
L1 = 1L_4.7uHInductor30%1.7Asmd
L2 = DA2304-ALB
L3 L21 L24-L26 L34 L35 = 1L_NFM21PC474_EMIFilter
L11 L33 = 1M_ACM2012
L12-L20 = 1L_1uHInductor20%4.5Alowprof
L22 = 1L_4.7uHInductor30%3.1Asmd
L28 = 1L_3.3uHInductor20%1.5Asmd
L29-L32 = 1M_DLW21SN900HQ2L: signal model: 1M_DLW21SN900HQ2L_DLW21SN900HQ2_DLW21SN900HQ2L
Q1-Q6 Q9-Q16 Q20-Q25 = 1Q_MOSFET_NChan_BSS138
Q7 Q8 = 1Q_MOSFET_PChan_FDT434P
Q26 Q27 = 1Q_MOSFET_PChan_FDT434P_1
R2 R10 R16-R18 R22 R32-R35 R37-R40 R45 R48 R107 R149 R153 R190 R233 R259 R299 R301 R306 R309 R343 R345 R352 R353 R364 R366 R397-R401 R412 R417 R420 R421 R425 R428 R430-R432 R453-R468 R485 R494 R496 R498 R539 R542-R546 R548 R549 R551 R553 R561 R570 R571 R637 R644 R645 R649 R654 R741 R789-R791 R798-R800 R804 R805 R833-R835 R894-R901 R911 R912 R924 R928 R931 = 1R_10KOhmResistor1/16W0402
R3 R281-R292 R325-R336 R426 = 1R_22OhmResistor1/16W1%0402: signal model: 1R_22OHMRESISTOR1/16W1%0402_SM-_22
R4 R305 R349 = 1MOhmResistor1/16W0402
R5-R9 R13-R15 R19 R20 R29 R67 R77 R78 R89 R93-R95 R106 R112 R114 R115 R117-R119 R121 R122 R134 R139 R148 R151 R154 R160 R161 R172 R176 R178 R188 R189 R195-R199 R202 R203 R214 R230 R231 R234 R241 R243 R247 R248 R253 R254 R273-R277 R294 R295 R300 R308 R312 R314 R338 R339 R351 R356 R358 R367 R369 R371 R377 R380 R381 R385 R387 R393 R394 R409-R411 R416 R418 R451 R473-R478 R480-R483 R486 R487 R489 R492 R497 R499 R500 R514 R547 R550 R554 R555 R557-R559 R564-R569 R572-R576 R582-R588 R590 R593 R594 R598 R600 R634 R636 R638 R643 R652 R653 R657-R666 R669-R673 R675-R679 R682-R686 R688-R692 R694 R698 R701 R703 R707 R710 R732-R734 R743-R753 R787 R792 R794-R797 R803 R807 R838-R893 R902-R910 R913-R921 R925 R929 R930 = 1R_ZeroOhmResistor1/16W0402
R11 R12 R429 R580 R581 R630-R633 R650 R655 R687 R788 R806 = 1R_100ohm1/16W1%SMD0402
R21 R304 R317 R319 R321 R348 R361 R363 = 1R_1KOhmResistor1/16W0402
R23-R28 R30 R31 R79-R88 R90-R92 R96 R98 R123-R130 R132 R133 R135-R137 R140 R142 R162-R171 R173-R175 R177 R179 R181 R204-R213 R215-R217 R219-R221 R223 R257 R258 R260-R265 R267 R269 R271 R402-R407 = 1R_ZeroOhmResistor1/16W0402: signal model: 1R_ZEROOHMRESISTOR1/16W0402_SM-_0
R36 R648 R923 = 1R_18.2Kohm1/16W1%smd0402
R41 R42 R44 = 1R_240OhmResistor1/16W0402
R46 R47 R99-R102 R143-R146 R182-R185 R224-R227 = 1R_49.9OhmResistor1/16W0402
R49-R55 R57-R66 R68 R70-R75 = 1R_47ohm1/16W1%smd0402
R56 R245 R246 R251 R252 R255 R256 R280 R324 R419 R515 R577 R578 R591 R592 R595 R597 R599 R695 R697 R700 R704 R706 R709 = 1R_100KOhmResistor1/16W0402
R69 R413 = 1R_10ohm1/16W5%smd0402
R76 R104 R108-R111 R116 R120 R131 R152 R155-R159 R187 R191-R194 R200 R201 R232 R235-R238 R383 R384 R495 R556 R563 R579 = 1R_2.2KOhmResistor1/16W0402
R97 R138 R141 R180 R218 R222 R278 R322 R472 R656 R742 = 1R_ZeroOhmResistor1/16W0603
R103 R147 R186 R228 = 1R_4.87Kohm1/16W1%smd0402
R113 = 1R_62OhmResistor1/16W0402
R239 R240 R242 R244 R249 R250 R386 R388-R392 R395 R396 R589 R596 R601-R604 R693 R696 R699 R702 R705 R708 = 1R_150ohm1/16W1%SMD0402
R279 = 1R_1.5KohmResistor1/16W5%0402
R293 R296 R337 R340 R493 = 1R_220ohm1/10W1%smd0402
R297 R342 R422 R423 R433 R450 R484 R491 R560 R562 = 1R_4.7KOhmResistor1/16W0402
R298 R341 = 1R_12.1KohmResistor1/16W1%0402
R310 R313 R315 R354 R357 R359 R502 R504 = 1R_33ohmResistor1/16W5%0402
R368 R370 R372-R376 R378 = 1R_1.2Kohm1/3W1%SMDMELF0102
R379 = 49.9ohm1/3W1%SMDMELF0102
R382 = 1R_25Kohm1/10W0.1%smd0603
R408 = 470Kohm1/16W1%SMD0402
R414 R927 = 1R_47KOhmResistor1/16W0402
R415 = 1R_2OhmResistor1/10W1%0603
R424 = 1R_1.62MOhmResistor1/16W0402
R427 = 1R_180KOhmResistor1/16W0402
R434-R449 = 1R_18KohmResistor1/10W1%smd0402
R479 = 1R_12Kohm1/16W1%SMD0402
R503 = 1R_120ohm1/16W1%smd0402
R505-R513 = 1R_49.9KOhmResistor1/16W0402
R639 = 1R_0.05ohm0.5W1%Sense1206
R640 = 1R_0.047ohm0.5W1%Sense1206
R641 = 1R_0.015ohm0.5W0.5%Sense1206
R642 = 1R_0.024ohm0.5W1%Sense1206
R646 = 1R_51Kohm1/16W1%smd0402
R647 = 1R_158Kohm1/16W1%smd0402
R680 = 1R_10KOhmResistor1/10W1%0402
R681 = 1R_19.6KohmResistor1/16W1%0402
R729 R730 = 1R_100ohm1/10W1%SMD0402
R793 R922 = 1R_20.5Kohm1/16W1%smd0402
R836 R837 = 1R_1MOhmResistor1/16W0402
SCKT1 = AM57XX_SOCKET
SW1-SW3 = 2W_Switch_Pushbuttonsmd
TP1 TP8-TP11 TP25 TP26 = 2H_TestPointThroughHole
TP2 TP3 TP6 TP7 TP16-TP24 TP27 = 2H_Testpoint_SMD1mmCircle
U1 = AM571X_ABCpkg_Industrial_10
U2 U22 U26 U28 U39 U47 U78 U96 U97 U99 = 1A_SN74LVC1G07
U3 = 1A_TPS659040_Indus_2
U4 = 1A_S25FL256S_QSPI
U5-U7 = 1A_MT41K256M16HA
U8 = TPS51200
U9 U13 U15 U17 = 1A_TLK105L
U18 = 1G_Haptics_Pico_304-100
U19 = 1A_SN74LVC1G04
U21 U24 = 1A_KSZ9031RNX
U23 U25 = 1A_CDCE913
U30 = 1A_TPD6E001RSE
U32 = 1A_TPS61081DRC
U33 = 1A_CAT24C256W
U34 = 1A_SN74LVC1G00DCK
U36 = 1A_TPD2E001DRL
U37 = 1A_FT2232_2
U38 = 1A_93C56EEPROM2Kbit
U40 = 1A_IsoReg5V_R1Z-3.305HP
U41 = 1A_ISO1050
U43 = 1A_EMMC16G_S100
U44 = 1A_SN74LVC1G125
U45 = 1A_CDCM9102
U46 = 1A_TPD12S016
U48-U50 U80-U84 U87 U88 = 1A_TPD1E10B06
U52 = TPS76650
U62 = 1A_TPS63010YFF
U63 = 1A_SN74AVC4T245
U64 = 1A_TPD2EUSB30DRT
U65 U75 = 1A_SN74AVC2T244
U66 = 1A_TPS2065D
U68-U71 U85 U98 = 1A_SN74LVC1G08DCKT_SC70
U72 = 1A_SN65HVS882
U73 = 1A_TPIC2810
U74 = 1A_ISO1176T
U76 = TPS71712
U77 = 1A_SN65HVD78
U79 = 1A_TPS61085
U86 = 1A_LP38693ADJ
